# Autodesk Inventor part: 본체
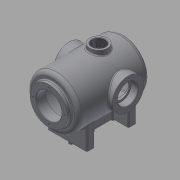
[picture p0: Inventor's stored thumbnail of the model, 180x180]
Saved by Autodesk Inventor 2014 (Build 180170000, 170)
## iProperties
Created: 2016-02
Part Number: 본체
Material: 알루미늄 6061
Document SubType Name: Modeling
Designer: mduedu
Density: 2.71 g/cm^3
Appearance: 기본값
Author: mduedu
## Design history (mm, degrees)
sketch "스케치2"
  geometry: L1 (0, 100)-(0, -100); L2 (65, -75.993)-(65, 100); L3 (65, 100)-(0, 100); A1 r 100 centre (0, 0) between (0, -100) and (65, -75.993); 2 further points
  constraints: 6 end point, 2 midpoint, 2 point on circle, 1 centre point, 1 coincident, 1 horizontal, 1 parallel, 1 vertical
  dimensions: "d3" = 200 distance of L1.start L1.end; "d5" = 130 diameter of L2 L1; "d6" = 100 radius of A1
revolve "회전1" sketch "스케치2" stored, may be unused: angle "d7" = 90 deg
sketch "스케치3"
  geometry: C1 r 47.5 at (0, 0); 1 further point
  constraints: 1 centre point, 1 coincident
  dimensions: "d8" = 95 diameter of C1
extrude "돌출2" join sketch "스케치3" distance "d10" = 10; taper "d11" = 0 deg
sketch "스케치5"
  geometry: L1 (47.5, 110)-(47.5, 100) reference; L2 (47.5, 100)-(65, 100) reference; L3 (65, 100)-(65, -75.993) reference; L4 (-65, -75.993)-(-65, 100) reference; L5 (-65, 100)-(-47.5, 100) reference; L6 (-47.5, 100)-(-47.5, 110) reference; L7 (-47.5, 110)-(47.5, 110) reference; L8 (55, 85)-(55, -71.239); L9 (0, 85)-(55, 85); L10 (0, 85)-(0, -90); A1 r 100 centre (0, 0) between (0, -100) and (65, -75.993) reference; A2 r 100 centre (0, 0) between (-65, -75.993) and (0, -100) reference; A3 r 90 centre (0, 0) between (0, -90) and (55, -71.239); 1 further point
  constraints: 6 end point, 2 point on circle, 1 centre point, 1 parallel, 1 perpendicular, 1 point on line, 1 vertical
  dimensions: "d13" = 10 distance between parallel lines of L3 L8; "d14" = 10 radial gap between concentric circles of A3 A1; "d15" = 15 distance between parallel lines of L9 L2
revolve "회전2" sketch "스케치5" stored, may be unused: angle "d16" = 90 deg
hole "구멍1" diameter "d19" = 65; stored, may be unused: countersink angle "d23" = 90 deg, drill point angle "d25" = 118 deg; dims "d17" = 10, "d18" = 10, "d20" = 6, "d21" = 4, "d22" = 2, "d24" = 8
node "작업 평면1"
sketch "스케치6"
  geometry: L1 (47.5, 110)-(-47.5, 110) reference; C1 r 40 at (0, -17); 1 further point
  constraints: 1 centre point, 1 vertical alignment
  dimensions: "d27" = 80 diameter of C1; "d29" = 127 distance from line of C1.centre L1
extrude "돌출3" join sketch "스케치6" stored distance "d30" = 10; taper "d31" = 0 deg
hole "구멍2" diameter "d34" = 42; stored, may be unused: countersink angle "d38" = 90 deg, drill point angle "d40" = 118 deg; dims "d32" = 10, "d33" = 10, "d35" = 6, "d36" = 52, "d37" = 18, "d39" = 8
sketch "스케치7" dims "d41" = 65
  geometry: C1 r 40 at (0, 0) reference; 3 further points
  constraints: 2 vertical alignment, 1 coincident, 2 other
hole "구멍3" sketch "스케치7" at (0, 32.5) diameter "d43" = 3.242; stored, may be unused: countersink angle "d47" = 90 deg, drill point angle "d49" = 118 deg; dims "d44" = 11, "d45" = 13, "d46" = 18, "d48" = 13
sketch "스케치8" dims "d53" = 80
  geometry: 3 further points
  constraints: 2 vertical alignment, 1 coincident, 2 other
hole "구멍4" sketch "스케치8" at (0, 40) diameter "d56" = 3.242; stored, may be unused: countersink angle "d60" = 90 deg, drill point angle "d62" = 118 deg; dims "d57" = 11, "d58" = 13, "d59" = 18, "d61" = 13
fillet "모깎기1" dims "d66" = 10
fillet "모깎기2" dims "d67" = 3
fillet "모깎기3" dims "d68" = 0.3
chamfer "모따기1" distance "d69" = 1; stored, may be unused: second distance "d70" = 2, angle "d71" = 45 deg
node "작업 평면5"
sketch "스케치10"
  geometry: L1 (-50, -63)-(50, -63); L2 (50, -63)-(50, -43); L3 (50, -43)-(-50, -43); L4 (-50, -43)-(-50, -63); L5 (-50, 0)-(50, 0); L6 (-50, 63)-(50, 63); L7 (50, 63)-(50, 43); L8 (50, 43)-(-50, 43); L9 (-50, 43)-(-50, 63); 2 further points
  constraints: 18 end point, 4 symmetric about line, 2 parallel, 2 perpendicular, 1 coincident, 1 horizontal, 1 midpoint
  dimensions: "d80" = 20 distance of L3.end L1.start; "d82" = 100 distance of L1.start L1.end; "d130" = 43 vertical distance of L3.end point (0, 0); "d131" = 50 horizontal distance of L3.end point (0, 0); "d132" = 100 distance of L5.start L5.end
extrude "돌출5" join sketch "스케치10" stored distance "d84" = 10; taper "d85" = 0 deg
sketch "스케치11"
  geometry: L1 (-100, -43)-(-100, 43); L2 (-65, 90)-(-65, -71.239) reference; L3 (-100, -43)-(-41.533, -43) reference; L4 (-100, 43)-(-41.533, 43) reference; 1 further point
  constraints: 2 end point, 1 point on line, 1 vertical
feature "리브1" sketch "스케치11" dims "d88" = 1, "d89" = 20, "d90" = 0, "d91" = 0, "d92" = 1, "d93" = 1
fillet "모깎기18" dims "d179" = 3
fillet "모깎기19" dims "d180" = 3
fillet "모깎기20" dims "d181" = 3
fillet "모깎기21" dims "d182" = 3
fillet "모깎기16" dims "d167" = 3
fillet "모깎기17" dims "d168" = 3
node "작업 평면6"
sketch "스케치19"
  geometry: L1 (75, -57)-(75, 23) reference; L2 (-75, -57)-(-75, 23) reference; L3 (75, -17)-(-75, -17); C1 r 22.5 at (0, -17); 1 further point
  constraints: 3 midpoint, 2 end point, 1 centre point
  dimensions: "d149" = 45 diameter of C1
extrude "돌출11" join sketch "스케치19" stored distance "d150" = 10; taper "d151" = 0 deg
hole "구멍6" diameter "d154" = 33.376; stored, may be unused: countersink angle "d158" = 90 deg, drill point angle "d160" = 118 deg; dims "d155" = 6, "d156" = 4, "d157" = 2, "d159" = 8, "d177" = 10, "d178" = 10
fillet "모깎기11" dims "d161" = 3
chamfer "모따기3" distance "d164" = 1; stored, may be unused: second distance "d165" = 2, angle "d166" = 45 deg
sketch "스케치20"
  geometry: L1 (10, 40)-(10, -40) reference; L2 (13, -43)-(47, -43) reference; L3 (-10, -40)-(-10, 40) reference; L4 (47, 43)-(13, 43) reference; L5 (-40, 53)-(40, 53); L6 (-40, -53)-(40, -53); L7 (0, 53)-(0, -53); L8 (50, -46)-(50, -60) reference; L9 (47, -63)-(-47, -63) reference; L10 (-50, -60)-(-50, -46) reference; L11 (-47, -43)-(-13, -43) reference; L12 (-13, 43)-(-47, 43) reference; L13 (-50, 46)-(-50, 60) reference; L14 (-47, 63)-(47, 63) reference; L15 (50, 60)-(50, 46) reference; C1 r 5 at (0, 53); C2 r 5 at (0, 0); C3 r 5 at (0, -53); A1 r 3 centre (13, -40) between (10, -40) and (13, -43) reference; A2 r 3 centre (-13, -40) between (-13, -43) and (-10, -40) reference; A3 r 3 centre (-13, 40) between (-10, 40) and (-13, 43) reference; A4 r 3 centre (13, 40) between (13, 43) and (10, 40) reference; A5 r 3 centre (47, -46) between (50, -46) and (47, -43) reference; A6 r 3 centre (47, -60) between (47, -63) and (50, -60) reference; A7 r 3 centre (-47, -60) between (-50, -60) and (-47, -63) reference; A8 r 3 centre (-47, -46) between (-47, -43) and (-50, -46) reference; A9 r 3 centre (-47, 46) between (-50, 46) and (-47, 43) reference; A10 r 3 centre (-47, 60) between (-47, 63) and (-50, 60) reference; A11 r 3 centre (47, 60) between (50, 60) and (47, 63) reference; A12 r 3 centre (47, 46) between (47, 43) and (50, 46) reference; 1 further point
  constraints: 6 end point, 3 centre point, 3 coincident, 2 midpoint, 2 parallel
  dimensions: "d169" = 10 diameter of C1; "d170" = 10 diameter of C2; "d171" = 10 diameter of C3
extrude "돌출12" join sketch "스케치20" distance "d172" = 10; taper "d173" = 0 deg
chamfer "모따기4" distance "d174" = 1; stored, may be unused: second distance "d175" = 2, angle "d176" = 45 deg
node "솔리드2"
pattern_circular "원형 패턴1" dims angle "d51" = 360 deg
mirror "대칭1"
pattern_circular "원형 패턴2" dims angle "d64" = 360 deg
node "절단 모서리 투영1"
node "절단 모서리 투영4"
other parameters: "d26" = 75, "d136" = 175
